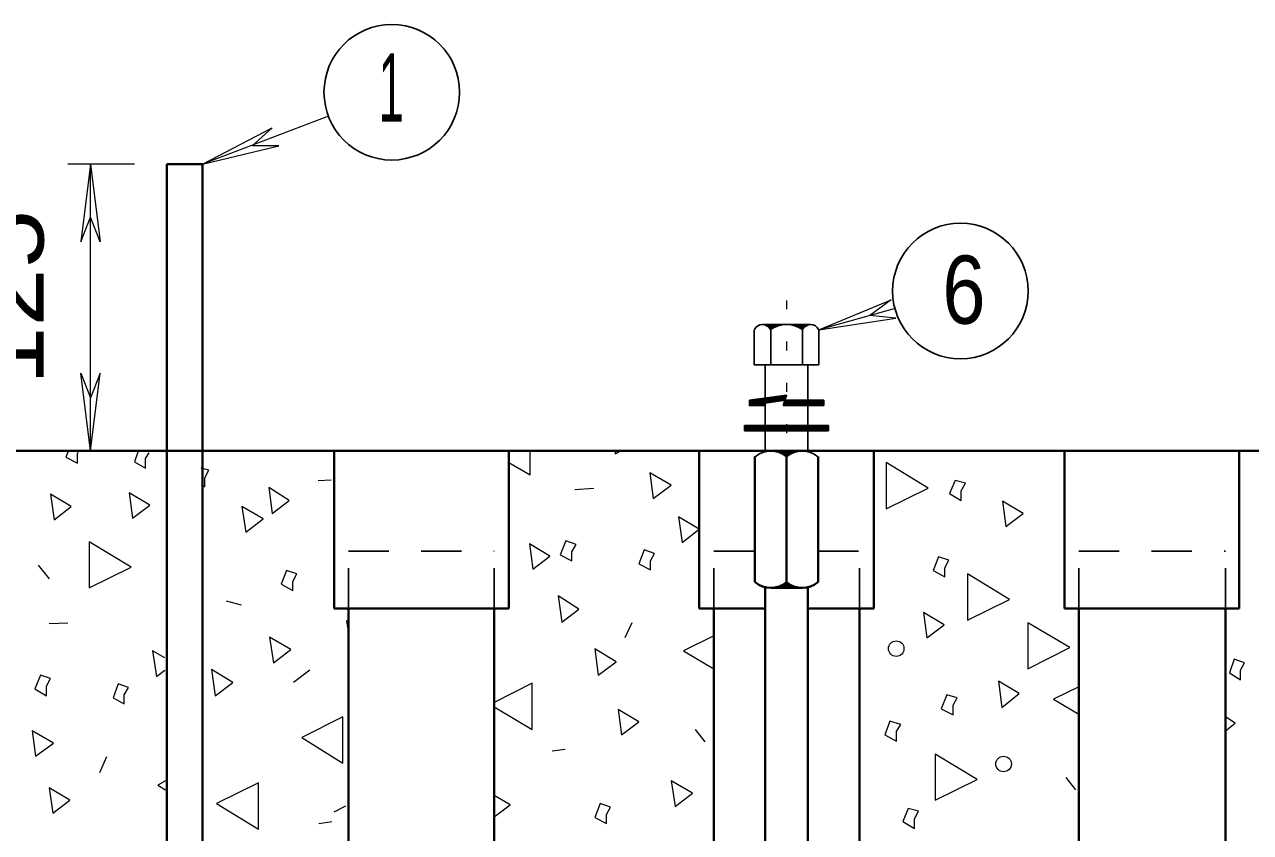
# Model space of a CAD drawing. Extents: x 312583 to 312854, y 144419 to 144597.
# Drawn here: x 312632.33 to 312645.99, y 144462.75 to 144471.76 of the extents above; entities that cross this region are included whole.
import ezdxf

# ---------------------------------------------------------------- set-up
doc = ezdxf.new("R2010")
doc.units = 0
doc.header["$LTSCALE"] = 0.3
doc.linetypes.add('DOTTED', pattern=[1.5, 0.3, -1.2])
doc.linetypes.add('SHORT_DASHED', pattern=[2.7, 1.5, -1.2])
doc.layers.add('1', color=7, linetype='Continuous', lineweight=25)
doc.layers.add('2', color=7, linetype='Continuous', lineweight=13)

msp = doc.modelspace()

# ---------------------------------------------------------------- linework, layer by layer
at = {"layer": '1', "lineweight": 40}
for p, q in [((312633.9126, 144470.2005), (312634.3113, 144470.2005)), ((312633.9126, 144470.2005), (312633.9126, 144459.6435)), ((312634.3113, 144470.2005), (312634.3113, 144458.6009)), ((312628.04, 144467.0035), (312653.6006, 144467.0035)), ((312635.7756, 144465.2479), (312635.7756, 144467.0035)), ((312637.723, 144465.2479), (312637.723, 144467.0035)), ((312639.8466, 144465.2479), (312639.8466, 144467.0035)), ((312640.4676, 144466.9422), (312640.4676, 144465.5392)), ((312640.8203, 144467.0035), (312640.8203, 144465.4779)), ((312641.173, 144466.9422), (312641.173, 144465.5392)), ((312641.794, 144465.2479), (312641.794, 144467.0035)), ((312643.9176, 144465.2479), (312643.9176, 144467.0035)), ((312645.865, 144465.2479), (312645.865, 144467.0035)), ((312640.5826, 144465.4779), (312640.5826, 144458.7005)), ((312640.644, 144465.4779), (312640.9966, 144465.4779)), ((312641.058, 144465.4779), (312641.058, 144459.1759)), ((312635.7756, 144465.2479), (312637.723, 144465.2479)), ((312635.9366, 144459.3369), (312635.9366, 144465.2479)), ((312637.562, 144459.3369), (312637.562, 144465.2479)), ((312639.8466, 144465.2479), (312640.5826, 144465.2479)), ((312640.0076, 144459.3369), (312640.0076, 144465.2479)), ((312641.058, 144465.2479), (312641.794, 144465.2479)), ((312641.633, 144459.3369), (312641.633, 144465.2479)), ((312643.9176, 144465.2479), (312645.865, 144465.2479)), ((312644.0786, 144459.3369), (312644.0786, 144465.2479)), ((312645.7116, 144459.3369), (312645.7116, 144465.2479))]:
    msp.add_line(p, q, dxfattribs=at)
at = {"layer": '1', "linetype": 'DOTTED', "lineweight": 13}
msp.add_line((312640.8203, 144468.6825), (312640.8203, 144467.0035), dxfattribs=at)
at = {"layer": '1'}
for p, q in [((312640.46, 144468.3529), (312640.46, 144467.9619)), ((312640.552, 144468.4142), (312641.0886, 144468.4142)), ((312640.644, 144468.3529), (312640.644, 144467.9619)), ((312640.9966, 144468.3529), (312640.9966, 144467.9619)), ((312641.1806, 144468.3529), (312641.1806, 144467.9619)), ((312640.46, 144467.9619), (312641.1806, 144467.9619)), ((312640.5826, 144467.9619), (312640.5826, 144467.0035)), ((312641.058, 144467.9619), (312641.058, 144467.0035)), ((312640.4063, 144467.5709), (312640.4063, 144467.5095)), ((312640.782, 144467.5095), (312641.2343, 144467.5095)), ((312640.805, 144467.5709), (312641.2343, 144467.5709)), ((312641.2343, 144467.5709), (312641.2343, 144467.5095)), ((312640.3526, 144467.2872), (312641.288, 144467.2872)), ((312640.3526, 144467.2872), (312640.3526, 144467.2259)), ((312640.3526, 144467.2719), (312641.288, 144467.2719)), ((312640.3526, 144467.2565), (312641.288, 144467.2565)), ((312640.3526, 144467.2412), (312641.288, 144467.2412)), ((312640.3526, 144467.2259), (312641.288, 144467.2259)), ((312641.288, 144467.2872), (312641.288, 144467.2259)), ((312640.5826, 144467.0035), (312641.058, 144467.0035)), ((312640.644, 144467.0035), (312640.9966, 144467.0035))]:
    msp.add_line(p, q, dxfattribs=at)
at = {"layer": '1', "lineweight": 13}
msp.add_line((312641.173, 144466.0605), (312641.1806, 144466.0529), dxfattribs=at)
at = {"layer": '1', "linetype": 'SHORT_DASHED'}
for p, q in [((312635.9366, 144465.8842), (312637.562, 144465.8842)), ((312635.9366, 144465.2479), (312635.9366, 144465.8842)), ((312637.562, 144465.2479), (312637.562, 144465.8842)), ((312640.0076, 144465.2479), (312640.0076, 144465.8842)), ((312640.0076, 144465.8842), (312640.4676, 144465.8842)), ((312641.173, 144465.8842), (312641.633, 144465.8842)), ((312641.633, 144465.2479), (312641.633, 144465.8842)), ((312644.0786, 144465.8842), (312645.7116, 144465.8842)), ((312644.0786, 144465.2479), (312644.0786, 144465.8842)), ((312645.7116, 144465.2479), (312645.7116, 144465.8842))]:
    msp.add_line(p, q, dxfattribs=at)
at = {"layer": '1'}
for points in [[(312640.575, 144468.4142), (312640.7743, 144468.4142), (312640.7436, 144468.4065), (312640.7206, 144468.3989), (312640.6823, 144468.3835), (312640.644, 144468.3605), (312640.6286, 144468.3835), (312640.6133, 144468.3912), (312640.5826, 144468.4065), (312640.759, 144468.4065), (312640.7053, 144468.3989), (312640.6746, 144468.3835), (312640.644, 144468.3682), (312640.6133, 144468.3912), (312640.598, 144468.4065), (312640.736, 144468.4065), (312640.69, 144468.3912), (312640.644, 144468.3682), (312640.6056, 144468.4065), (312640.7206, 144468.4065), (312640.644, 144468.3759), (312640.6133, 144468.3989), (312640.7053, 144468.4065), (312640.6363, 144468.3759), (312640.621, 144468.3989), (312640.69, 144468.3989), (312640.644, 144468.3835), (312640.6286, 144468.3989), (312640.6746, 144468.3989), (312640.644, 144468.3835), (312640.6363, 144468.3989), (312640.6593, 144468.3912), (312640.644, 144468.3912)], [(312641.0656, 144468.4142), (312640.8663, 144468.4142), (312640.897, 144468.4065), (312640.92, 144468.3989), (312640.9583, 144468.3835), (312640.9966, 144468.3605), (312641.012, 144468.3835), (312641.0273, 144468.3912), (312641.058, 144468.4065), (312640.8816, 144468.4065), (312640.9353, 144468.3989), (312640.966, 144468.3835), (312640.9966, 144468.3682), (312641.0273, 144468.3912), (312641.0426, 144468.4065), (312640.9046, 144468.4065), (312640.9506, 144468.3912), (312640.9966, 144468.3682), (312641.035, 144468.4065), (312640.92, 144468.4065), (312640.9966, 144468.3759), (312641.0273, 144468.3989), (312640.9353, 144468.4065), (312640.9966, 144468.3759), (312641.0196, 144468.3989), (312640.9506, 144468.3989), (312640.9966, 144468.3835), (312641.012, 144468.3989), (312640.966, 144468.3989), (312640.9966, 144468.3835), (312641.0043, 144468.3989), (312640.9813, 144468.3912), (312640.9966, 144468.3912)], [(312640.4063, 144467.5709), (312640.8203, 144467.6245), (312640.782, 144467.5095)], [(312640.5826, 144467.5095), (312640.4063, 144467.5172), (312640.414, 144467.5632), (312640.8126, 144467.6169), (312640.7973, 144467.5709), (312640.575, 144467.5402), (312640.575, 144467.5172), (312640.414, 144467.5249), (312640.4216, 144467.5555), (312640.7973, 144467.6092), (312640.7896, 144467.5785), (312640.5673, 144467.5402), (312640.5673, 144467.5249), (312640.4216, 144467.5325), (312640.4216, 144467.5479), (312640.782, 144467.6015), (312640.782, 144467.5862), (312640.5673, 144467.5479), (312640.5596, 144467.5402), (312640.5136, 144467.5325), (312640.4293, 144467.5402), (312640.7743, 144467.5939), (312640.483, 144467.5402)], [(312640.805, 144467.5709), (312640.4063, 144467.5095), (312640.5826, 144467.5095)], [(312640.7973, 144467.5172), (312641.2266, 144467.5172), (312641.2266, 144467.5632), (312640.8126, 144467.5555), (312640.7973, 144467.5249), (312641.219, 144467.5249), (312641.219, 144467.5555), (312640.8126, 144467.5479), (312640.805, 144467.5325), (312641.2113, 144467.5325), (312641.2036, 144467.5402), (312641.2036, 144467.5479), (312640.8203, 144467.5479), (312640.8126, 144467.5402), (312641.2036, 144467.5402)], [(312640.69, 144467.0035), (312640.9506, 144467.0035), (312640.92, 144466.9959), (312640.897, 144466.9882), (312640.8663, 144466.9729), (312640.8433, 144466.9652), (312640.8203, 144466.9499), (312640.8203, 144466.9422), (312640.7743, 144466.9729), (312640.7283, 144466.9959), (312640.7053, 144466.9959), (312640.9353, 144467.0035), (312640.9123, 144466.9959), (312640.897, 144466.9959), (312640.8663, 144466.9805), (312640.8356, 144466.9652), (312640.828, 144466.9575), (312640.8203, 144466.9499), (312640.7743, 144466.9805), (312640.7283, 144466.9959), (312640.897, 144466.9959), (312640.8586, 144466.9805), (312640.8203, 144466.9575), (312640.7436, 144466.9959), (312640.8816, 144466.9959), (312640.8203, 144466.9575), (312640.759, 144466.9882), (312640.8663, 144466.9959), (312640.8203, 144466.9652), (312640.782, 144466.9882), (312640.851, 144466.9882), (312640.8203, 144466.9805), (312640.782, 144466.9805), (312640.805, 144466.9729), (312640.8126, 144466.9882), (312640.8203, 144466.9652), (312640.8356, 144466.9805), (312640.8433, 144466.9805), (312640.8586, 144466.9882)]]:
    msp.add_lwpolyline(points, dxfattribs=at)
at = {"layer": '1', "lineweight": 40}
msp.add_lwpolyline([(312640.69, 144465.4779), (312640.9506, 144465.4779), (312640.92, 144465.4855), (312640.897, 144465.4932), (312640.8663, 144465.5009), (312640.8433, 144465.5162), (312640.8203, 144465.5315), (312640.8203, 144465.5315), (312640.7743, 144465.5009), (312640.7283, 144465.4855), (312640.7053, 144465.4779), (312640.9353, 144465.4779), (312640.9123, 144465.4855), (312640.897, 144465.4855), (312640.8663, 144465.4932), (312640.8356, 144465.5085), (312640.828, 144465.5239), (312640.8203, 144465.5315), (312640.7743, 144465.5009), (312640.7283, 144465.4855), (312640.897, 144465.4855), (312640.8586, 144465.4932), (312640.8203, 144465.5239), (312640.7436, 144465.4855), (312640.8816, 144465.4855), (312640.8203, 144465.5239), (312640.759, 144465.4855), (312640.8663, 144465.4855), (312640.8203, 144465.5162), (312640.782, 144465.4932), (312640.851, 144465.4932), (312640.8203, 144465.5009), (312640.782, 144465.4932), (312640.805, 144465.5085), (312640.8126, 144465.4932), (312640.8203, 144465.5162), (312640.8356, 144465.5009), (312640.8433, 144465.5009), (312640.8586, 144465.4932)], dxfattribs=at)
at = {"layer": '1'}
for centre, radius, start, end in [((312640.551, 144468.3133), 0.0993, 25.60064, 154.39936), ((312640.8197, 144468.1), 0.3126, 55.04559, 124.95441), ((312641.0883, 144468.3133), 0.0993, 25.60064, 154.39936), ((312640.6448, 144466.7308), 0.272, 50.00693, 129.99306), ((312640.9944, 144466.7308), 0.272, 50.00694, 129.99307)]:
    msp.add_arc(centre, radius, start, end, dxfattribs=at)
at = {"layer": '1', "lineweight": 40}
for centre, start, end in [((312640.6448, 144465.7482), 230.00694, 309.99307), ((312640.9944, 144465.7482), 230.00693, 309.99306)]:
    msp.add_arc(centre, 0.272, start, end, dxfattribs=at)
msp.add_spline([(312648.0653, 144467.0035), (312648.5713, 144466.1372), (312649.1693, 144465.2479), (312648.8243, 144464.1745), (312648.257, 144463.7375), (312648.004, 144462.8175), (312647.8813, 144460.6095), (312647.3446, 144459.5362), (312647.1836, 144459.3445), (312646.2636, 144458.5549), (312645.7116, 144458.7849), (312644.8453, 144458.6775), (312644.0786, 144458.7465), (312643.22, 144458.5319), (312642.162, 144458.4935), (312641.5333, 144458.7005), (312640.805, 144458.3939), (312640.713, 144458.3019), (312640.0076, 144458.4092), (312638.9113, 144457.7345), (312638.6276, 144457.6732), (312637.562, 144458.2329), (312635.9673, 144458.3095), (312635.6223, 144457.8495)], degree=3, dxfattribs=at)
at = {"layer": '2'}
for p, q in [((312635.7143, 144470.7372), (312634.3113, 144470.2005)), ((312634.3113, 144470.2005), (312635.0856, 144470.6069)), ((312635.0856, 144470.6069), (312634.8633, 144470.4075)), ((312634.3113, 144470.2005), (312635.1623, 144470.4075)), ((312635.1623, 144470.4075), (312634.8633, 144470.4075)), ((312633.5523, 144470.2005), (312632.8086, 144470.2005)), ((312633.0616, 144470.2005), (312632.9543, 144469.3342)), ((312633.0616, 144467.0035), (312633.0616, 144470.2005)), ((312633.0616, 144470.2005), (312633.169, 144469.3342)), ((312632.9543, 144469.3342), (312633.0616, 144469.6102)), ((312633.169, 144469.3342), (312633.0616, 144469.6102)), ((312641.1806, 144468.3529), (312641.9856, 144468.6902)), ((312641.9856, 144468.6902), (312641.748, 144468.5139)), ((312642.0316, 144468.5905), (312641.1806, 144468.3529)), ((312641.1806, 144468.3529), (312642.0393, 144468.4832)), ((312642.0393, 144468.4832), (312641.748, 144468.5139)), ((312632.9543, 144467.8699), (312633.0616, 144467.5939)), ((312633.0616, 144467.0035), (312632.9543, 144467.8699)), ((312633.169, 144467.8699), (312633.0616, 144467.5939)), ((312633.0616, 144467.0035), (312633.169, 144467.8699)), ((312632.916, 144466.9729), (312632.9236, 144466.9882)), ((312633.675, 144466.9192), (312633.7133, 144466.9805)), ((312637.9606, 144466.7352), (312637.9606, 144467.0035)), ((312637.723, 144466.8732), (312637.9606, 144466.7352)), ((312635.5993, 144466.6739), (312635.745, 144466.6815)), ((312638.459, 144466.5742), (312638.6736, 144466.5895)), ((312637.723, 144465.9225), (312637.723, 144465.9302)), ((312632.479, 144465.7309), (312632.6016, 144465.5775)), ((312634.572, 144465.3322), (312634.7406, 144465.2862)), ((312632.6016, 144465.0792), (312632.8086, 144465.0869)), ((312639.0953, 144465.0869), (312639.0186, 144464.9182)), ((312633.7976, 144464.4889), (312633.8896, 144464.5579)), ((312635.5073, 144464.5579), (312635.3233, 144464.4199)), ((312637.562, 144464.1515), (312637.9836, 144463.8985)), ((312639.8006, 144463.8985), (312639.908, 144463.7605)), ((312638.206, 144463.6609), (312638.3516, 144463.6762)), ((312633.238, 144463.5919), (312633.1613, 144463.4155)), ((312643.933, 144463.3619), (312644.0403, 144463.2239)), ((312635.7756, 144462.9785), (312635.906, 144463.0475)), ((312635.607, 144462.8482), (312635.7526, 144462.8712))]:
    msp.add_line(p, q, dxfattribs=at)
for points in [[(312632.8086, 144466.9882), (312632.7856, 144466.9345), (312632.916, 144466.8655), (312632.916, 144466.9729)], [(312633.5906, 144466.9882), (312633.5523, 144466.8809), (312633.675, 144466.8119), (312633.675, 144466.9192)], [(312638.9113, 144467.0035), (312638.9113, 144466.9729), (312638.965, 144467.0035)], [(312634.3343, 144466.7045), (312634.3803, 144466.7889), (312634.296, 144466.8119)], [(312634.296, 144466.6202), (312634.3343, 144466.6049), (312634.3343, 144466.7045)], [(312635.9366, 144465.0945), (312635.9136, 144465.1099), (312635.9366, 144464.9719)], [(312640.0076, 144464.9412), (312639.6703, 144464.7725), (312640.0076, 144464.5732)], [(312633.8896, 144464.6959), (312633.7516, 144464.7725), (312633.7976, 144464.4889)], [(312637.9836, 144463.8985), (312637.9836, 144464.4122), (312637.562, 144464.1975)], [(312644.0786, 144464.3739), (312643.795, 144464.2359), (312644.0786, 144464.0672)], [(312645.7116, 144463.8832), (312645.819, 144463.9675), (312645.7116, 144464.0365)], [(312633.8973, 144463.3235), (312633.813, 144463.2775), (312633.8973, 144463.2239)], [(312637.562, 144462.9249), (312637.7383, 144463.0552), (312637.562, 144463.1625)]]:
    msp.add_lwpolyline(points, dxfattribs=at)
for points in [[(312641.932, 144466.8732), (312641.932, 144466.3595), (312642.3996, 144466.5895)], [(312639.333, 144466.4745), (312639.5323, 144466.6202), (312639.2946, 144466.7582)], [(312642.7676, 144466.5589), (312642.8136, 144466.6432), (312642.6986, 144466.6739), (312642.6373, 144466.5282), (312642.7676, 144466.4515)], [(312632.6553, 144466.2369), (312632.847, 144466.3825), (312632.617, 144466.5205)], [(312633.5293, 144466.2522), (312633.721, 144466.3979), (312633.491, 144466.5359)], [(312635.0856, 144466.3059), (312635.2773, 144466.4515), (312635.0473, 144466.5972)], [(312634.7943, 144466.0989), (312634.986, 144466.2445), (312634.7483, 144466.3825)], [(312643.266, 144466.1602), (312643.4576, 144466.3059), (312643.2276, 144466.4439)], [(312639.655, 144465.9839), (312639.8466, 144466.1295), (312639.6166, 144466.2675)], [(312633.0463, 144465.9915), (312633.0463, 144465.4779), (312633.514, 144465.7079)], [(312637.9913, 144465.6849), (312638.183, 144465.8305), (312637.953, 144465.9685)], [(312638.4283, 144465.8765), (312638.4743, 144465.9609), (312638.3593, 144465.9992), (312638.298, 144465.8459), (312638.4283, 144465.7769)], [(312639.3023, 144465.7769), (312639.3483, 144465.8612), (312639.2333, 144465.8995), (312639.172, 144465.7462), (312639.3023, 144465.6772)], [(312642.5836, 144465.7002), (312642.6296, 144465.7845), (312642.5146, 144465.8229), (312642.4533, 144465.6695), (312642.5836, 144465.6005)], [(312635.3156, 144465.5469), (312635.3616, 144465.6312), (312635.2466, 144465.6695), (312635.1853, 144465.5162), (312635.3156, 144465.4472)], [(312642.8366, 144465.6312), (312642.8366, 144465.1175), (312643.3043, 144465.3475)], [(312638.3133, 144465.0945), (312638.505, 144465.2402), (312638.275, 144465.3859)], [(312642.3843, 144464.9182), (312642.576, 144465.0639), (312642.346, 144465.2019)], [(312643.5113, 144465.0869), (312643.5113, 144464.5732), (312643.979, 144464.8109)], [(312635.101, 144464.6422), (312635.2926, 144464.7879), (312635.055, 144464.9259)], [(312638.7196, 144464.5042), (312638.919, 144464.6499), (312638.6813, 144464.7955)], [(312645.8803, 144464.5579), (312645.9263, 144464.6422), (312645.8113, 144464.6805), (312645.7576, 144464.5272), (312645.8803, 144464.4505)], [(312632.571, 144464.3815), (312632.617, 144464.4659), (312632.502, 144464.5042), (312632.4406, 144464.3509), (312632.571, 144464.2742)], [(312634.4493, 144464.2742), (312634.6486, 144464.4199), (312634.411, 144464.5655)], [(312633.4373, 144464.2819), (312633.4833, 144464.3662), (312633.3683, 144464.4045), (312633.3146, 144464.2512), (312633.4373, 144464.1822)], [(312643.22, 144464.1439), (312643.4116, 144464.2972), (312643.1816, 144464.4352)], [(312642.6756, 144464.1669), (312642.7216, 144464.2512), (312642.6066, 144464.2819), (312642.5453, 144464.1285), (312642.6756, 144464.0595)], [(312638.9803, 144463.8372), (312639.172, 144463.9829), (312638.942, 144464.1209)], [(312635.8753, 144463.5229), (312635.8753, 144464.0365), (312635.4153, 144463.8065)], [(312642.047, 144463.8755), (312642.093, 144463.9522), (312641.9703, 144463.9905), (312641.9166, 144463.8372), (312642.047, 144463.7682)], [(312632.4483, 144463.5995), (312632.6476, 144463.7452), (312632.41, 144463.8832)], [(312642.4763, 144463.6225), (312642.4763, 144463.1089), (312642.944, 144463.3389)], [(312632.64, 144462.9632), (312632.8316, 144463.1089), (312632.6016, 144463.2469)], [(312634.9323, 144462.7869), (312634.9323, 144463.3005), (312634.4646, 144463.0705)], [(312639.5783, 144463.0399), (312639.77, 144463.1855), (312639.5323, 144463.3235)], [(312638.8116, 144462.9479), (312638.8576, 144463.0322), (312638.7426, 144463.0705), (312638.6813, 144462.9172), (312638.8116, 144462.8482)], [(312642.2463, 144462.9019), (312642.2923, 144462.9862), (312642.1773, 144463.0169), (312642.116, 144462.8712), (312642.2463, 144462.7945)]]:
    msp.add_lwpolyline(points, close=True, dxfattribs=at)
at = {"layer": '2', "lineweight": 25}
for centre in [(312636.4196, 144471.003), (312642.7581, 144468.7867)]:
    msp.add_circle(centre, 0.7557, dxfattribs=at)
at = {"layer": '2'}
for centre in [(312642.0427, 144464.7991), (312643.2394, 144463.5124)]:
    msp.add_circle(centre, 0.0865, dxfattribs=at)

# ---------------------------------------------------------------- texts
for s, width, p in [('1', 0.5, (312636.2724, 144470.6755)), ('6', 0.85, (312642.557, 144468.4224))]:
    msp.add_text(s, height=0.76, dxfattribs=dict(at, width=width)).set_placement(p)
at = {"layer": '2', "width": 1.15}
msp.add_text('125 ', height=0.76, rotation=90, dxfattribs=at).set_placement((312632.538, 144467.7403))

doc.saveas('drawing.dxf')
